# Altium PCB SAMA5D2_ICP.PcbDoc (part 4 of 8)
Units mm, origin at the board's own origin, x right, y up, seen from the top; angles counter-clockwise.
Board outline 150 x 100 mm, 6 copper layers (L1 - TOP, L2 - GND, L3 - SIG, L4 - SIG, L5 - VCC, L6 - BOT), stack 1.512 mm thick; 708 components, 597 nets, 2710 pads, 1437 vias.
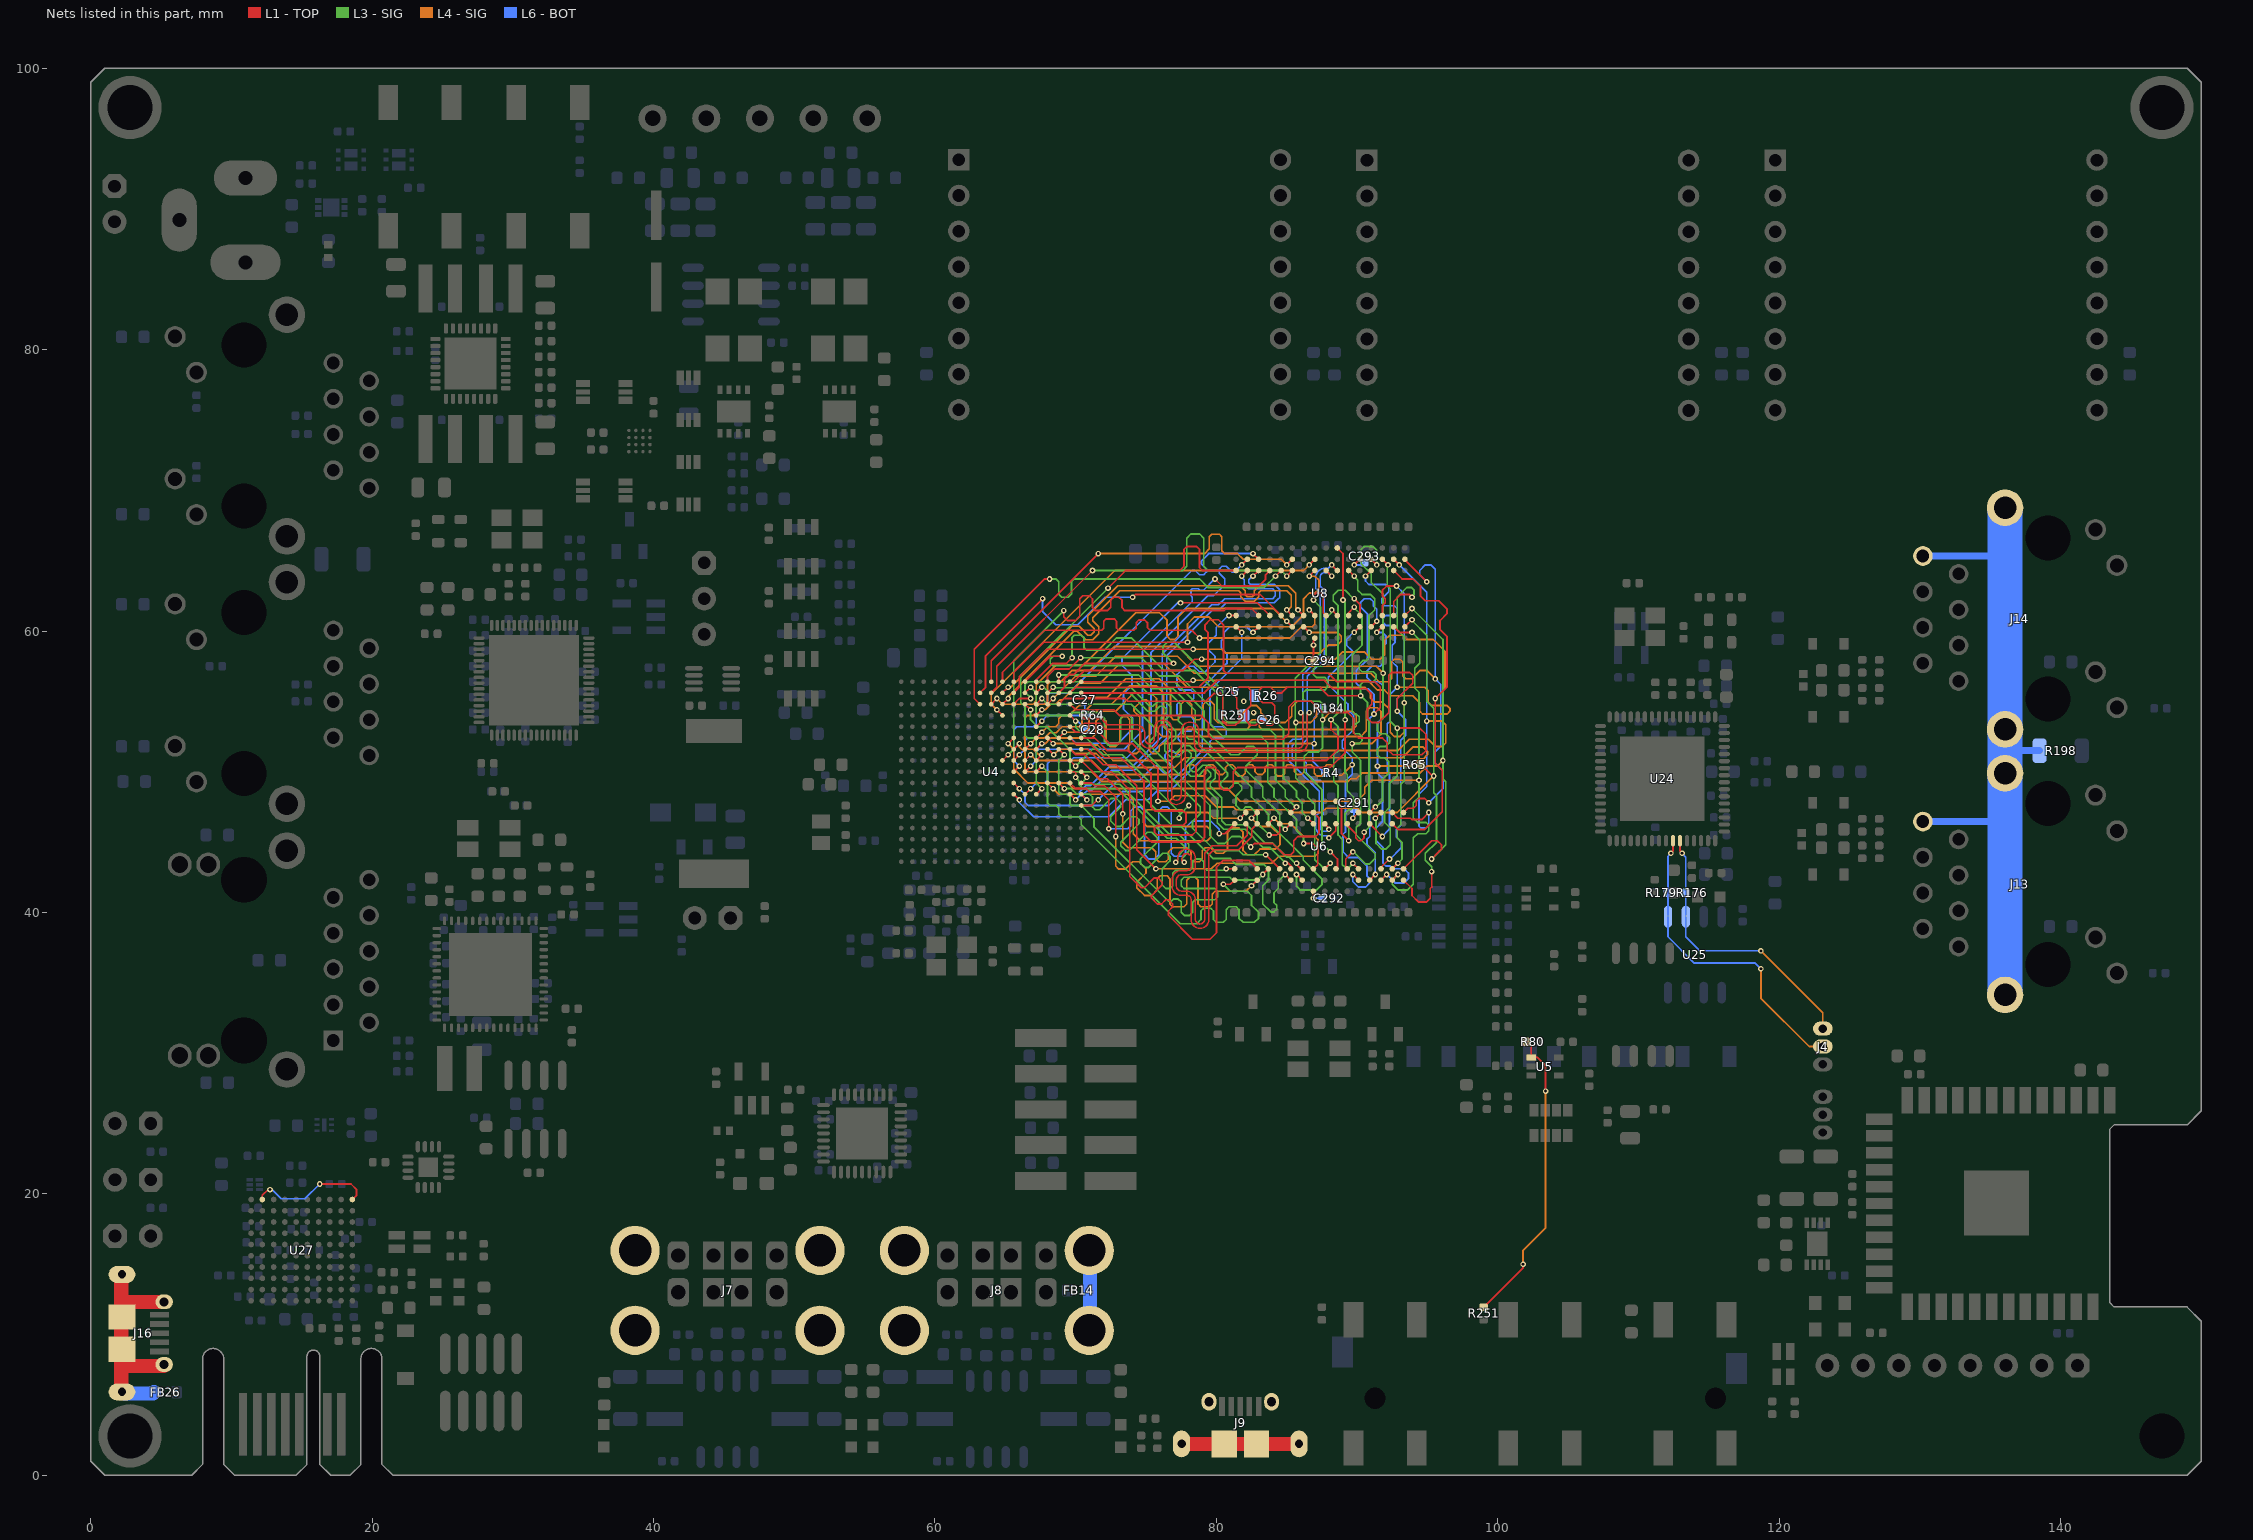
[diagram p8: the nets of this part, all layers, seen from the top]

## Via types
v1: diameter 0.4, hole 0.2, L1 - TOP to L6 - BOT, tented both sides, 1312 vias
v2: diameter 0.55, hole 0.3, L1 - TOP to L6 - BOT, 84 vias
v3: diameter 0.4, hole 0.2, L1 - TOP to L6 - BOT, tented top, 25 vias
v4: diameter 0.55, hole 0.3, L1 - TOP to L6 - BOT, tented bottom, 16 vias

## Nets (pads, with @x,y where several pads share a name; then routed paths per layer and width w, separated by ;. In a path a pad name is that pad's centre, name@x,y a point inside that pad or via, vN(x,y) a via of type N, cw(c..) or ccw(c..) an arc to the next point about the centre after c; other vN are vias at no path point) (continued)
DDR_A2: U4.B17 U6.P3 U8.P3 | length 57.6
  L1 - TOP w0.125: U4.B17@70.4,55.6 79.15,55.6 80.05,56.5 87.65,56.5 88.25,55.9 90.65,55.9 91.05,55.5 91.05,54.793 90.75,54.493 90.75,53.8 91.05,53.5 91.55,53.5 92.25,54.2 92.25,56.85 92.45,57.05 93.75,57.05 93.95,56.85 93.95,56.3 92.85,55.2 v1(92.85,54.3) ; U6.P3@91.7,43.1 91.7,43.2 v1(92.3,43.8) ; U8.P3@91.8,61.1 91.8,61.8 92,62 92,62.3 91.8,62.5 91.8,62.9 92.1,63.2 v1(92.8,63.2)
  L6 - BOT w0.125: v1@92.35,43.8 93.15,44.6 93.15,44.993 92.8,45.343 92.8,45.9 93.1,46.2 93.1,52.25 93.45,52.6 93.45,53.7 v1(92.85,54.3) 92.85,55.2 93.35,55.7 93.35,62.65 v1(92.8,63.2)
DDR_A3: U4.B16 U6.N2 U8.N2 | length 57.5
  L1 - TOP w0.125: U4.B16@69.6,55.6 70,56 78.75,56 79.4,56.65 79.4,59.9 79.2,60.1 79.2,60.45 79.55,60.8 80.15,60.8 80.5,60.45 80.5,57.2 80.7,57 87.95,57 88.55,56.4 91.25,56.4 91.65,56 91.65,54.55 v1(91.2,54.1) ; U6.N2@90.9,42.3 v1(91.3,42.7) ; U8.N2@91,60.3 v1(91.4,60.7)
  L6 - BOT w0.125: v1(91.3,42.7) 91.3,44.25 90.7,44.85 90.7,45.2 90.9,45.4 90.9,53.8 v1(91.2,54.1) 91.2,55.5 90.8,55.9 90.35,55.9 89.95,56.3 89.95,57.193 90.75,57.993 90.75,61.2 90.25,61.7 90.25,62.05 90.5,62.3 90.95,62.3 91.15,62.1 91.15,61.8 91.4,61.55 v1(91.4,60.7)
DDR_A4: U4.C16 U6.P8 U8.P8 | length 60
  L1 - TOP w0.125: U4.C16@69.6,54.8 70,54.4 72.7,54.4 73.1,54 78.9,54 79.45,53.45 79.45,52.55 79.7,52.3 84.75,52.3 85.15,52.7 85.15,54.6 85.55,55 86.75,55 87.55,54.2 89.357,54.2 89.75,53.807 89.75,52.75 90.1,52.4 91.8,52.4 92.15,52.05 92.15,51.6 92.55,51.2 94.6,51.2 94.9,51.5 94.9,52.65 94.45,53.1 v1(92.85,53.1) ; v1(91.3,46.7) U6.P8@91.7,47.1 ; U8.P8@91.8,65.1 v1(92.2,64.7)
  L3 - SIG w0.125: v1@91.35,46.7 91.35,44.9 91.75,44.5 92.05,44.5 92.35,44.8 92.35,46 91.95,46.4 91.95,47.1 92.3,47.45 92.3,49.15 92.85,49.7 v1(92.85,53.1) 92.35,53.6 92.35,63.009 92.15,63.209 v1@92.15,64.7
DDR_A5: U4.G14 U6.P2 U8.P2 | length 57.5
  L1 - TOP w0.125: U4.G14@68.05,51.6 v1(68.45,51.2) ; v1(91.4,59.9) U8.P2@91.8,60.3 ; U6.P2@91.7,42.3 v1(92.1,42.7)
  L4 - SIG w0.125: v1(68.45,51.2) 68.85,51.6 69.65,51.6 69.95,51.3 71.45,51.3 72.45,50.3 77.05,50.3 77.75,51 93.2,51 93.95,51.75 94.7,51.75 95,51.45 95,51.2 94.7,50.9 94.4,50.9 93.9,50.4 v1(91.45,50.4)
  L6 - BOT w0.125: v1(91.4,59.9) 91.8,59.9 92.05,59.65 92.05,59.1 91.85,58.9 91.85,57.7 91.65,57.5 91.05,57.5 90.7,57.15 90.7,56.7 91,56.4 91.55,56.4 91.85,56.1 91.85,53.9 91.45,53.5 v1(91.45,50.4) 91.45,49.9 91.8,49.55 91.8,46.45 91.35,46 91.35,45.1 91.85,44.6 91.85,43.5 92.05,43.3 92.35,43.3 92.55,43.1 93.35,43.1 93.65,42.8 93.65,42.4 93.35,42.1 92.7,42.1 v1(92.1,42.7)
DDR_A6: U4.F14 U6.R8 U8.R8 | length 57.6
  L1 - TOP w0.125: U4.F14@68,52.4 v1(68.4,52) ; U6.R8@92.5,47.1 92.9,46.7 93.8,46.7 93.9,46.6 94.6,46.6 v1(95.1,47.1) v1@95.1,47.125 ; U8.R8@92.6,65.1 v1(93,64.7)
  L4 - SIG w0.125: v1(68.4,52) 69.95,52 70.05,51.9 71.557,51.9 72.657,50.8 76.75,50.8 77.45,51.5 92.9,51.5 93.7,52.3 95.05,52.3 95.55,51.8 96.06,51.8 96.3,52.04 96.3,53.325 96.025,53.6 v1(94.95,53.6)
  L6 - BOT w0.125: v1(93,64.7) 94.95,62.75 v1(94.95,53.6) 94.95,48.95 94.4,48.4 94.4,46.128 94.528,46 94.922,46 95.1,46.178 v1(95.1,47.1)
DDR_A7: U4.F11 U6.R2 U8.R2 | length 58.1
  L1 - TOP w0.125: v1(65.2,52) U4.F11@65.6,52.4 ; U6.R2@92.5,42.3 v1(92.9,42.7) ; U8.R2@92.6,60.3 93,59.9 v1(93.9,59.9)
  L3 - SIG w0.125: v1(92.9,42.7) 92.5,42.3 92.5,42 92.9,41.6 93.6,41.6 94,42 94,45.3 94.3,45.6 94.9,45.6 95.1,45.8 95.1,46.2 94.9,46.4 94.3,46.4 94,46.7 94,47.8 94.4,48.2 v1(94.4,49.4) 94.4,55.65 94.1,55.95 94.1,57.35 94.45,57.7 94.45,59.35 v1(93.9,59.9)
  L4 - SIG w0.125: v1(65.2,52) 65.6,51.6 65.6,50.2 66.6,49.2 69.45,49.2 69.85,48.8 80.8,48.8 81.7,47.9 90,47.9 90.55,48.45 90.55,48.9 91.05,49.4 v1(94.4,49.4)
DDR_A8: U4.C14 U6.T8 U8.T8 | length 57.4
  L1 - TOP w0.125: U4.C14@68,54.8 v1(68.4,55.2) ; U8.T8@93.35,65.1 v1(94.95,63.5) ; U6.T8@93.4,47.2 93.6,47.4 94,47.4 94.2,47.6 94.2,47.9 94.4,48.1 94.8,48.1 v1(95.1,47.8)
  L4 - SIG w0.125: v1(68.4,55.2) 70,56.8 71.45,56.8 72.85,58.2 77.236,58.2 78.436,57 90.964,57 ; 90.964,56.996 91.56,56.4 92.25,56.4 92.45,56.6 92.45,57.8 92.65,58 93.05,58 93.25,57.8 93.25,56.8 93.45,56.6 93.9,56.6 94.5,57.2 94.95,57.2 v1(95.55,56.6)
  L6 - BOT w0.125: v1(94.95,63.5) 94.45,64 94.45,64.3 94.85,64.7 95.25,64.7 95.55,64.4 v1(95.55,56.6) 95.95,56.2 95.95,51.8 95.45,51.3 95.45,50.7 96.1,50.05 96.1,48.8 v1(95.1,47.8)
DDR_A9: U4.D13 U6.R3 U8.R3 | length 58.1
  L1 - TOP w0.125: U4.D13@67.2,54 v1(67.6,54.4) ; U6.R3@92.5,43.1 v1(92.9,43.5) ; U8.R3@92.6,61.1 92.6,62.1 93.1,62.6 93.7,62.6 v1(93.9,62.4)
  L3 - SIG w0.125: v1(92.9,43.5) 93.2,43.8 93.2,44.95 92.85,45.3 92.85,46 93.1,46.25 93.1,49.1 93.35,49.35 v1(93.35,54.9) 93.35,59.6 92.85,60.1 92.85,62.4 93.55,63.1 93.85,63.1 94.05,62.9 94.05,62.6 v1@93.85,62.4
  L4 - SIG w0.125: v1(67.6,54.4) 67.834,54.4 68.234,54.8 68.566,54.8 68.866,55.1 69.05,55.1 70.25,56.3 71.75,56.3 73.15,57.7 76.243,57.7 77.943,56 90.543,56 90.946,55.596 90.946,55.25 91.246,54.95 91.8,54.95 92.35,54.4 92.35,52.8 92.65,52.5 93.043,52.5 93.35,52.807 v1(93.35,54.9)
DDR_A10: U4.C15 U6.L7 U8.L7 | length 60
  L1 - TOP w0.125: U4.C15@68.8,54.8 69.2,55.2 73.5,55.2 73.7,55 79.257,55 79.807,55.55 80.3,55.55 80.45,55.4 80.45,53.6 80.75,53.3 81.35,53.3 81.65,53.6 81.65,54.3 81.45,54.5 81.45,55.25 81.15,55.55 81.15,55.8 81.35,56 82.25,56 82.45,55.8 82.45,54.707 82.15,54.407 82.15,53.6 82.45,53.3 82.8,53.3 83.1,53.6 83.3,53.6 83.6,53.3 83.95,53.3 84.15,53.5 84.15,54.7 83.95,54.9 83.3,54.9 83.05,55.15 83.05,55.8 83.25,56 83.85,56 84.25,55.6 84.65,55.6 85.05,56 87.35,56 87.95,55.4 v1(90.25,55.4) ; U6.L7@89.3,46.2 89.9,45.6 89.9,45.3 90.1,45.1 90.3,45.1 90.5,45.3 v1(90.5,45.7) ; U8.L7@89.4,64.3 v1(89.8,63.9)
  L3 - SIG w0.125: v1@89.75,63.9 90.05,63.6 90.05,62.9 90.35,62.6 90.95,62.6 91.25,62.3 91.25,61.493 90.85,61.093 90.85,58.1 90.65,57.9 90.4,57.9 90.15,57.65 90.15,57.3 90.35,57.1 91.15,57.1 91.35,56.9 91.35,56.6 91.15,56.4 90.45,56.4 90.25,56.2 v1(90.25,55.4) 90.75,54.9 90.75,53.7 90.85,53.6 90.85,46.05 v1(90.5,45.7)
DDR_A11: U4.A16 U6.R7 U8.R7 | length 58.1
  L1 - TOP w0.125: U4.A16@69.6,56.4 69.85,56.4 70.65,57.2 77.65,57.2 78.45,58 v1(78.95,58) ; U6.R7@92.5,46.3 92.9,45.9 94.8,45.9 96.05,47.15 96.05,50.1 95.55,50.6 v1(95.55,55.2) 96.4,56.05 96.4,59.6 95.9,60.1 95.9,60.75 96.4,61.25 96.4,61.55 95.8,62.15 94.85,62.15 94.5,62.5 94.5,63.2 94,63.7 93.2,63.7 U8.R7@92.6,64.3
  L4 - SIG w0.125: v1(78.95,58) 88.45,58 88.95,58.5 90.55,58.5 91.05,58 91.65,58 91.95,58.3 91.95,59.325 92.325,59.7 93.25,59.7 93.55,59.4 95.4,59.4 96.25,58.55 96.25,55.9 v1(95.55,55.2)
DDR_A12: U4.A17 U6.N7 U8.N7 | length 57.6
  L1 - TOP w0.125: U4.A17@70.4,56.4 78.25,56.4 v1(78.35,56.5) ; v1(90.6,63.9) U8.N7@91,64.3 ; U6.N7@90.9,46.3 v1(91.8,45.4)
  L4 - SIG w0.125: v1(78.35,56.5) 90.75,56.5 91.45,55.8 91.95,55.8 92.35,55.4 93.95,55.4 94.45,54.9 94.45,54.3 94.65,54.1 96.4,54.1 96.6,54.3 96.6,54.5 96.4,54.7 95.3,54.7 95.05,54.95 95.05,55.75 94.8,56 v1(92.85,56)
  L6 - BOT w0.125: v1(90.6,63.9) 90.6,63.55 90.85,63.3 92.05,63.3 92.25,63.1 92.25,62.8 91.75,62.3 91.75,62 91.95,61.8 92.65,61.8 92.85,61.6 92.85,61.3 92.65,61.1 92.05,61.1 91.85,60.9 91.85,60.6 92.05,60.4 92.35,60.4 92.7,60.05 92.7,59.2 92.5,59 92.5,57.8 92.85,57.45 v1(92.85,56) 92.35,55.5 92.35,53.6 92.15,53.4 92.15,50 92.3,49.85 92.3,45.9 v1(91.8,45.4)
DDR_A13: U4.G11 U6.T3 U8.T3 | length 58.1
  L1 - TOP w0.125: U4.G11@65.6,51.6 v1(66,52) ; U6.T3@93.3,43.1 95.3,45.1 95.7,45.1 96,44.8 96,44.5 95.8,44.3 v1(95.3,43.8) ; U8.T3@93.4,61.1 v1(93.9,61.6)
  L3 - SIG w0.125: v1(93.9,61.6) 96.1,59.4 v1(96.1,50.8) 96.1,49.5 96.3,49.3 96.3,44.8 v1(95.3,43.8)
  L4 - SIG w0.125: v1(66,52) 66,51.775 66.4,51.375 66.4,50.2 66.6,50 71.15,50 71.85,49.3 89.343,49.3 89.543,49.5 89.95,49.5 90.35,49.9 94.45,49.9 94.95,50.4 95.7,50.4 v1(96.1,50.8)
DDR_BA0: U4.H12 U6.M2 U8.M2 | length 57.6
  L1 - TOP w0.125: U4.H12@66.4,50.8 v1(66.8,51.2) ; v1(89.7,42.7) U6.M2@90.1,42.3 ; v1(89.8,59.9) U8.M2@90.2,60.3
  L4 - SIG w0.125: v1(66.8,51.2) 67.2,50.8 71.15,50.8 71.45,50.5 72.15,49.8 77.65,49.8 77.85,50 77.85,50.3 78.05,50.5 78.35,50.5 78.55,50.3 78.55,49.89 78.75,49.69 79.05,49.69 79.25,49.89 79.25,50.3 79.45,50.5 79.75,50.5 79.95,50.3 79.95,50 80.15,49.8 80.45,49.8 80.65,50 80.65,50.3 80.85,50.5 81.15,50.5 81.35,50.3 81.35,49.89 81.55,49.69 81.85,49.69 82.05,49.89 82.05,50.3 82.25,50.5 82.55,50.5 82.75,50.3 ; 82.75,50.3 82.75,50 82.95,49.8 83.25,49.8 83.45,50 83.45,50.3 83.65,50.5 83.95,50.5 84.15,50.3 84.15,49.89 84.35,49.69 84.65,49.69 84.85,49.89 84.85,50.3 85.05,50.5 85.35,50.5 85.55,50.3 85.55,50 85.75,49.8 86.05,49.8 86.25,50 86.25,50.3 86.45,50.5 86.75,50.5 86.95,50.3 86.95,49.89 87.15,49.69 87.45,49.69 87.65,49.89 87.65,50.3 87.85,50.5 88.15,50.5 88.35,50.3 88.35,49.9 88.5,49.75 88.9,49.75 v1(89.65,50.5)
  L6 - BOT w0.125: v1(89.7,42.7) 89.7,42.2 90.1,41.8 90.6,41.8 90.9,42.1 90.9,42.4 90.7,42.6 90.7,43.3 90.1,43.9 89.4,43.9 89,44.3 89,45.55 89.175,45.725 89.175,49.35 89.65,49.825 v1(89.65,50.5) 89.65,51.01 88.95,51.71 88.95,52.19 89.75,52.99 89.75,54 89.35,54.4 89.35,54.81 87.96,56.2 87.95,56.2 87.95,56.7 89.65,58.4 89.65,58.6 89.25,59 89.25,59.4 v1@89.75,59.9
DDR_BA1: U4.H13 U6.N8 U8.N8 | length 57.9
  L1 - TOP w0.125: U4.H13@67.2,50.8 v1(67.6,51.2) ; U6.N8@90.9,47.1 v1(91.3,47.5) ; U8.N8@91,65.1 v1(91.4,64.7)
  L3 - SIG w0.125: v1@91.35,47.5 91.8,47.95 91.8,49.45 92.25,49.9 92.25,50.7 91.95,51 91.65,51 91.45,51.2 91.45,51.6 91.65,51.8 92.05,51.8 92.3,52.05 92.3,52.45 92.05,52.7 91.65,52.7 91.45,52.9 91.45,53.4 91.85,53.8 v1(91.85,57) 91.85,62.6 91,63.45 91,64.066 90.3,64.766 90.3,65.8 90.5,66 91.15,66 91.4,65.75 v1(91.4,64.7)
  L4 - SIG w0.125: v1(67.6,51.2) 67.374,51.2 66.974,51.6 66.634,51.6 66.4,51.834 66.4,53.825 66.575,54 67,54 67.2,54.2 67.2,54.6 67.4,54.8 67.775,54.8 68,55.025 68,56.175 68.225,56.4 68.95,56.4 69.75,57.2 71.05,57.2 72.75,58.9 77.243,58.9 78.643,57.5 91.35,57.5 v1(91.85,57)
DDR_BA2: U4.F17 U6.M3 U8.M3 | length 59.9
  L1 - TOP w0.125: U4.F17@70.4,52.4 71.35,52.4 72.25,51.5 73.75,51.5 75.35,49.9 75.35,47.5 75.65,47.2 77.65,47.2 77.85,47 77.85,46.4 77.65,46.2 75.802,46.2 75.602,46 75.602,45.7 75.802,45.5 78.3,45.5 78.55,45.75 78.55,50.4 78.95,50.8 87.85,50.8 88.65,51.6 88.65,52.5 88.15,53 v1(88.15,53.7) ; v1(89.7,43.5) U6.M3@90.1,43.1 ; v1(89.8,62.3) 90.2,61.9 U8.M3@90.2,61.1
  L3 - SIG w0.125: v1@89.725,43.475 89.45,43.2 89.15,43.2 88.95,43.4 88.95,45.2 88.65,45.5 88.65,49.007 88.35,49.307 88.35,51.2 88.65,51.5 88.65,53.2 v1(88.15,53.7) 88.65,54.2 88.65,61.8 88.3,62.15 88.3,62.55 88.65,62.9 89.15,62.9 v1@89.75,62.3
DDR_CAL: C27.2 R64.2 U4.E13 | length 4.4
  L1 - TOP w0.125: U4.E13@67.2,53.2 v1(67.6,53.6)
  L6 - BOT w0.125: v1(67.6,53.6) 68,54 R64.2@70.55,54 ; R64.2@70.65,54.1 C27.2@70.65,54.8
DDR_CAS: U4.G12 U6.K3 U8.K3 | length 58
  L1 - TOP w0.125: U4.G12@66.4,51.6 v1(66.8,52) ; v1(88.1,44.3) 88.6,43.8 U6.K3@88.6,43.2 ; v1(88.2,61.5) U8.K3@88.6,61.1
  L3 - SIG w0.125: v1(88.1,44.3) 87.5,44.9 87.5,48.75 86.25,50 86.25,51.1 86.55,51.4 87.25,51.4 87.55,51.7 v1(87.55,53.7) 87.55,54.8 87.35,55 86.35,55 86.15,55.2 86.15,55.6 86.35,55.8 87.7,55.8 87.9,56 87.9,56.5 87.7,56.7 87.1,56.7 86.9,56.9 86.9,57.3 87.1,57.5 87.5,57.5 87.8,57.8 87.8,60.916 88.15,61.266 v1@88.15,61.5
  L4 - SIG w0.125: v1(66.8,52) 67.2,52.4 67.775,52.4 68.15,52.775 68.609,52.775 69.034,53.2 70.25,53.2 70.45,53.4 70.45,54.1 71.15,54.8 72.55,54.8 73.85,56.1 75.722,56.1 76.25,55.572 76.25,53.2 76.45,53 80.55,53 82.15,53 82.35,53.2 82.35,53.5 82.55,53.7 82.85,53.7 83.05,53.5 83.05,53.2 83.25,53 89.7,53 89.95,53.25 89.95,54 89.65,54.3 88.15,54.3 v1(87.55,53.7)
DDR_CKE: U4.F16 U6.K9 U8.K9 | length 60
  L1 - TOP w0.125: U4.F16@69.6,52.4 70,52 71.05,52 72.05,51 73.225,51 74.85,49.375 74.85,45.55 75.4,45 78.845,45 79.15,45.305 79.15,50.05 79.4,50.3 79.9,50.3 80.2,50 80.2,49 80.5,48.7 80.9,48.7 81.2,49 81.2,50 81.5,50.3 88.1,50.3 89.15,51.35 v1(89.15,53.7) ; U6.K9@88.5,47.9 88.9,47.5 88.9,45.6 v1(89.4,45.1) ; U8.K9@88.6,65.9 89,65.5 v1(89,62.2)
  L3 - SIG w0.125: v1(89,62.2) 89.15,62.05 v1(89.15,53.7) 89.15,49.95 89.3,49.8 89.3,48.65 89.75,48.2 89.75,47.5 89.55,47.3 89.4,47.3 89.15,47.05 89.15,46.25 89.4,46 v1(89.4,45.1)
DDR_CLK_N: U4.D17 U6.K7 U8.K7 | length 57.3
  L1 - TOP w0.102: U4.D17@70.4,54 70.648,53.752 71.823,53.752 72.244,53.331 74.294,53.331 cw(c74.294,52.7) 74.924,52.7 74.924,52.3 ccw(c75.25,52.3) 75.25,51.974 ccw(c75.25,52.3) 75.576,52.3 75.576,53.026 cw(c76.207,53.026) 76.207,53.656 cw(c76.207,53.026) 76.837,53.026 76.837,48.3 ccw(c77.163,48.3) 77.163,47.974 ccw(c77.163,48.3) 77.489,48.3 77.489,52.884 cw(c78.119,52.884) 78.119,53.515 cw(c78.119,52.884) 78.75,52.884 78.75,52 ccw(c79.076,52) 79.076,51.674 79.35,51.674 85.824,51.674 ccw(c85.824,52) 86.15,52 86.15,54.05 v1(86,54.2) ; v1@88.1,45.4 88.5,45.8 U6.K7@88.5,46.3 ; v1(88.2,64.7) U8.K7@88.5,64.4
  L6 - BOT w0.102: v1(86,54.2) v1@86.145,54.2 ; v1(88,45.3) 87.853,45.448 87.7,45.448 cw(c87.7,46.078) 87.069,46.078 87.069,46.869 87.295,47.095 87.295,48.605 85.1,50.8 85.1,51.981 85.419,52.3 86,52.3 86.145,52.445 v1@86.145,54.2 ; v1(88.2,64.7) 87.952,64.452 87.7,64.452 ccw(c87.7,63.822) 87.069,63.822 87.069,63.05 87.37,62.749 87.37,58.12 86.145,56.895 v1@86.145,54.2
DDR_CLK_P: U4.E17 U6.J7 U8.J7 | length 57.1
  L1 - TOP w0.102: U4.E17@70.4,53.2 70.648,53.448 71.696,53.448 72.118,53.026 74.294,53.026 cw(c74.294,52.7) 74.62,52.7 74.62,52.3 ccw(c75.25,52.3) 75.25,51.669 ccw(c75.25,52.3) 75.881,52.3 75.881,53.026 cw(c76.207,53.026) 76.207,53.352 cw(c76.207,53.026) 76.532,53.026 76.532,48.3 ccw(c77.163,48.3) 77.163,47.669 ccw(c77.163,48.3) 77.794,48.3 77.794,52.884 cw(c78.119,52.884) 78.119,53.21 cw(c78.119,52.884) 78.445,52.884 78.445,52 ccw(c79.076,52) 79.076,51.369 79.35,51.369 85.824,51.369 ccw(c85.824,52) 86.455,52 86.455,54.055 v1(86.6,54.2) ; U6.J7@87.7,46.3 88,46 v1(88,45.9) ; U8.J7@87.8,64.3 v1(88.2,63.9)
  L6 - BOT w0.102: v1(86.6,54.2) v1@86.45,54.2 ; v1(88,45.9) 87.853,45.752 87.7,45.752 cw(c87.7,46.078) 87.374,46.078 87.374,46.743 87.6,46.969 87.6,49.2 87.4,49.4 86.931,49.4 86.4,49.931 86.4,50.639 86.239,50.8 85.531,50.8 85.405,50.926 85.405,51.855 85.545,51.995 86.126,51.995 86.45,52.319 v1@86.45,54.2 ; v1(88.2,63.9) 87.952,64.148 87.7,64.148 ccw(c87.7,63.822) 87.374,63.822 87.374,63.176 87.675,62.875 87.675,57.994 86.45,56.769 v1@86.45,54.2
DDR_CS: R4.1 R184.1 U4.G13 | length 40.4
  L1 - TOP w0.125: U4.G13@67.2,51.6 v1(67.6,52)
  L4 - SIG w0.125: v1(67.6,52) 67.834,52 68.234,52.4 71.15,52.4 71.45,52.7 71.45,53.6 71.65,53.8 71.95,53.8 72.15,53.6 72.15,52.1 72.45,51.8 72.85,51.8 73.15,52.1 73.15,53.7 73.35,53.9 73.65,53.9 73.85,53.7 73.85,51.9 73.75,51.8 73.75,51.5 73.95,51.3 74.35,51.3 74.55,51.5 74.55,53.9 74.15,54.3 74.15,54.5 74.75,55.1 75.05,55.1 75.25,54.9 75.25,51.5 75.45,51.3 75.75,51.3 75.95,51.5 75.95,51.8 76.15,52 v1(86.95,52)
  L6 - BOT w0.125: R184.1@87.6,54.5 86.95,53.85 v1(86.95,52) 86.85,51.9 86.85,50.75 R4.1@87.7,49.9
DDR_D0: U4.B12 U6.E3 | length 30.7
  L1 - TOP w0.125: U4.B12@66.4,55.6 v1(66.8,56) ; v1(83.5,44.1) U6.E3@84.5,43.1
  L3 - SIG w0.125: v1(66.8,56) 67.2,55.6 67.2,54.225 67.425,54 69.55,54 69.75,54.2 71.65,54.2 72.05,53.8 72.05,52.15 72.3,51.9 72.9,51.9 73.2,52.2 73.2,53.8 73.4,54 73.8,54 74,53.8 74,52.35 78.85,47.5 78.85,47 78.3,46.45 78.3,46 79.9,44.4 81.6,44.4 81.9,44.1 v1(83.5,44.1)
DDR_D1: U4.A12 U6.F7 | length 30.8
  L1 - TOP w0.125: U4.A12@66.4,56.4 68.2,58.2 v1(69.05,58.2) ; v1(84.9,45.9) U6.F7@85.3,46.3
  L3 - SIG w0.125: v1(69.05,58.2) 68.4,58.2 68.2,58 68.2,57.7 68.35,57.55 74.466,57.55 75.65,56.366 77.084,56.366 79.116,54.334 79.116,53.109 81.025,51.2 81.6,51.2 82.2,51.8 82.626,51.8 82.9,51.526 82.9,51.2 82.1,50.4 82.1,50.125 83.3,48.925 83.3,48.2 84.5,47 84.5,46.3 v1(84.9,45.9)
DDR_D2: U4.C12 U6.F2 | length 30.8
  L1 - TOP w0.125: U4.C12@66.4,54.8 v1(66.8,54.4) ; v1(84.9,42.7) U6.F2@85.3,42.3
  L3 - SIG w0.125: v1(66.8,54.4) 66.8,53.687 67.288,53.2 67.95,53.2 69.6,51.55 69.6,50.225 69.825,50 73.043,50 76.943,46.1 77.5,46.1 79.775,43.825 81,43.825 81.425,43.4 83.4,43.4 83.7,43.1 83.7,42.3 83.3,41.9 83.3,40.6 83.863,40.037 84.1,40.037 84.3,40.237 84.3,40.5 84.1,40.7 84.1,41.4 84.4,41.7 84.4,42.2 v1(84.9,42.7)
DDR_D3: U4.A13 U6.F8 | length 30.8
  L1 - TOP w0.125: U4.A13@67.2,56.4 67.2,56.54 68.36,57.7 69.35,57.7 v1(69.75,58.1) ; U6.F8@85.3,47.1 v1(85.7,47.5)
  L3 - SIG w0.125: v1(69.75,58.1) 69.75,59.55 69.9,59.7 70.407,59.7 70.6,59.507 70.6,58.8 70.775,58.625 72.025,58.625 72.907,59.507 73.943,59.507 76.25,57.2 78.434,57.2 80.05,55.584 80.05,53.734 80.784,53 83.8,53 84.2,52.6 84.2,49.4 84.9,48.7 84.9,48.2 85.6,47.5 v1(85.7,47.5)
DDR_D4: U4.A14 U6.H3 | length 30.7
  L1 - TOP w0.125: U4.A14@68,56.4 68,56.775 68.525,57.3 69.55,57.3 v1(70.35,58.1) ; v1(86.2,44.9) 86.85,44.9 87.2,44.55 87.2,43.4 U6.H3@86.9,43.1
  L3 - SIG w0.125: v1(70.35,58.1) 74.65,58.1 75.95,56.8 77.4,56.8 79.6,54.6 79.6,53.35 80.45,52.5 83.2,52.5 83.658,52.042 83.658,49.242 84.1,48.8 84.1,48.2 85.7,46.6 85.7,45.8 86.2,45.3 v1(86.2,44.9)
DDR_D5: U4.C13 U6.H8 | length 30.7
  L1 - TOP w0.125: U4.C13@67.2,54.8 v1(67.6,55.2) ; v1(82.45,44.65) 82.7,44.9 84.013,44.9 84.813,44.1 85.3,44.1 85.5,44.3 85.5,45.105 85.795,45.4 87.05,45.4 87.3,45.65 87.3,46.7 U6.H8@86.9,47.1
  L3 - SIG w0.125: v1(67.6,55.2) 68,54.8 73.95,54.8 75.7,53.05 75.7,52.6 75.3,52.2 75.3,51.85 79.55,47.6 79.55,45.45 80.1,44.9 80.6,44.9 81.1,45.4 81.7,45.4 v1(82.45,44.65)
DDR_D6: U4.A15 U6.G2 | length 30.8
  L1 - TOP w0.125: U4.A15@68.8,56.4 v1(68.8,56.875) ; v1(85.7,42.7) U6.G2@86.1,42.3
  L3 - SIG w0.125: v1(68.8,56.875) 74.475,56.875 75.45,55.9 76.95,55.9 78.5,54.35 78.5,52.9 82.5,48.9 82.5,48.2 83.7,47 83.7,46.425 86.175,43.95 86.175,43.725 87.5,42.4 87.5,41.975 87.125,41.6 85.95,41.6 85.7,41.85 v1(85.7,42.7)
DDR_D7: U4.B15 U6.H7 | length 30.8
  L1 - TOP w0.125: U4.B15@68.8,55.6 69.2,56 69.2,56.566 69.534,56.9 69.857,56.9 70.657,57.7 v1(76.95,57.7) ; v1(86.5,46.7) U6.H7@86.9,46.3
  L3 - SIG w0.125: v1(76.95,57.7) 76.2,58.45 76.2,58.9 76.5,59.2 77,59.2 80.45,55.75 80.45,53.9 80.85,53.5 84.3,53.5 84.775,53.025 84.775,49.525 85.7,48.6 85.7,48.2 85.9,48 86.1,47.8 86.1,47.1 v1(86.5,46.7)
DDR_D8: U4.G17 U6.D7 | length 28.7
  L1 - TOP w0.125: U4.G17@70.4,51.6 70.85,51.6 71.95,50.5 72.85,50.5 74.35,49 74.35,44.45 v1(75.7,43.1) ; U6.D7@83.7,46.3 v1(84.1,46.7)
  L4 - SIG w0.125: v1(75.7,43.1) 79.65,43.1 80.05,43.5 83.95,43.5 84.45,44 87,44 87.224,44.224 87.224,45.176 87,45.4 86.2,45.4 85.3,46.3 84.5,46.3 v1(84.1,46.7)
DDR_D9: U4.G16 U6.C3 | length 31.3
  L1 - TOP w0.125: U4.G16@69.6,51.6 70,51.2 70.65,51.2 71.85,50 72.55,50 73.85,48.7 73.85,42.55 74.65,41.75 74.891,41.75 75.595,42.455 75.855,42.455 76.155,42.155 76.155,41.955 75.4,41.2 75.4,41 75.8,40.6 76.1,40.6 76.4,40.9 76.6,40.9 76.9,40.6 76.9,40.4 76.6,40.1 76.6,39.8 78.3,38.1 79.55,38.1 80.012,38.562 80.012,43.212 80.5,43.7 82.3,43.7 U6.C3@82.9,43.1
DDR_D10: U4.H17 U6.C8 | length 28.8
  L1 - TOP w0.125: U4.H17@70.4,50.8 71.7,49.5 72.257,49.5 73.35,48.407 v1(73.35,47) ; v1(82.5,46.7) U6.C8@82.9,47.1
  L4 - SIG w0.125: v1(73.35,47) 73.35,45 73.75,44.6 75.4,44.6 75.7,44.3 75.7,43.8 75.9,43.6 76.4,43.6 76.6,43.8 76.6,44.3 76.9,44.6 77.9,44.6 78.2,44.3 78.2,43.8 78.4,43.6 78.8,43.6 79,43.8 79,44.4 79.2,44.6 79.6,44.6 80,44.2 80.5,44.2 80.8,44.5 80.8,45.7 81.1,46 81.6,46 81.9,45.7 81.9,44.4 82.2,44.1 82.7,44.1 83.1,44.5 84.2,44.5 84.531,44.831 84.531,45.469 83.9,46.1 83.1,46.1 82.525,46.675 v1(82.5,46.7)
DDR_D11: U4.K17 U6.C2 | length 28.8
  L1 - TOP w0.125: U4.K17@70.4,49.2 71.15,49.2 71.35,49 72.05,49 72.85,48.2 v1(72.85,45.4) ; v1(82.5,41.9) U6.C2@82.9,42.3
  L4 - SIG w0.125: v1(72.85,45.4) 72.85,43.3 73.072,43.078 73.528,43.078 74.05,43.6 74.5,43.6 75,43.1 75,42.8 74.35,42.15 74.35,41.75 74.9,41.2 75.4,41.2 75.8,41.6 75.8,42.4 76,42.6 76.5,42.6 76.7,42.4 76.7,40.6 76.9,40.4 77.7,40.4 77.9,40.6 77.9,42.3 78.1,42.5 78.5,42.5 78.7,42.3 78.7,40.6 78.9,40.4 79.5,40.4 79.7,40.6 79.7,41.301 79.9,41.501 82.101,41.501 v1(82.5,41.9)
DDR_D12: U4.K16 U6.A7 | length 28.3
  L1 - TOP w0.125: U4.K16@69.6,49.2 70,48.8 70.75,48.8 70.95,48.6 71.743,48.6 72.35,47.993 v1(72.35,45.95) ; v1(80.2,45.6) 80.6,45.6 U6.A7@81.3,46.3
  L6 - BOT w0.125: v1(72.35,45.95) 73.7,45.95 73.9,46.15 73.9,47.2 74.2,47.5 74.6,47.5 74.9,47.2 74.9,44.1 75.2,43.8 75.6,43.8 75.9,44.1 75.9,47.2 76.2,47.5 76.5,47.5 76.8,47.2 76.8,44.2 77,44 77.6,44 77.8,44.2 77.8,46 78.3,46.5 79.6,46.5 80.2,45.9 v1(80.2,45.6)
DDR_D13: U4.J13 U6.A2 | length 30.8
  L1 - TOP w0.125: U4.J13@67.2,50 v1(67.6,50.4) ; v1(80.5,42) 81,42 U6.A2@81.3,42.3
  L3 - SIG w0.125: v1(67.6,50.4) 68,50 68,47.8 68.2,47.6 68.6,47.6 68.8,47.4 68.8,47 69,46.8 69.4,46.8 70.2,46.8 70.4,46.6 70.4,46.234 70.634,46 70.641,46 77.441,39.2 78.6,39.2 78.9,39.5 78.9,40.1 79.1,40.3 79.6,40.3 79.8,40.1 79.8,39.5 80,39.3 80.5,39.3 80.7,39.5 80.7,40.2 80.9,40.4 81.4,40.4 81.6,40.2 81.6,39.6 81.9,39.3 82.7,39.3 83,39.6 83,40 82.5,40.5 82.5,41.2 82.2,41.5 81,41.5 v1(80.5,42)
DDR_D14: U4.K14 U6.B8 | length 28.8
  L1 - TOP w0.125: U4.K14@68,49.2 v1(68.4,48.8) ; v1(81.7,46.7) U6.B8@82.1,47.1
  L4 - SIG w0.125: v1(68.4,48.8) 68.8,48.4 73.7,48.4 74.1,48 74.1,45.6 74.6,45.1 79.35,45.1 79.604,45.354 79.604,45.846 79.35,46.1 75.1,46.1 74.8,46.4 74.8,47 75.1,47.3 77.55,47.3 77.75,47.1 79.4,47.1 79.8,46.7 v1(81.7,46.7)
DDR_D15: U4.K15 U6.A3 | length 30.8
  L1 - TOP w0.125: U4.K15@68.8,49.2 v1(69.2,48.8) ; v1(80.7,43.1) U6.A3@81.3,43.1
  L3 - SIG w0.125: v1(69.2,48.8) 69.7,48.8 70.1,48.4 71,48.4 71.2,48.2 71.2,47.5 71.4,47.3 71.7,47.3 72.5,48.1 72.9,48.1 73.2,47.8 73.2,47.5 72.5,46.8 72.5,46.5 72.9,46.1 73.165,46.1 73.865,46.8 74.3,46.8 74.5,46.6 74.5,46.3 73.2,45 73.2,44.75 73.55,44.4 73.8,44.4 75.1,45.7 75.4,45.7 75.8,45.3 75.8,45 74.6,43.8 74.6,43.5 74.9,43.2 75.2,43.2 76.2,44.2 76.5,44.2 76.7,44 76.7,43.659 76.149,43.108 76.149,41.951 76.4,41.7 76.7,41.7 76.9,41.9 76.9,42.8 77.1,43 78.1,43 78.3,43.2 78.3,43.6 78.5,43.8 78.9,43.8 79.1,43.6 79.1,43.2 79.3,43 80.6,43 v1(80.7,43.1)
DDR_D16: U4.B8 U8.E3 | length 28.3
  L1 - TOP w0.125: U4.B8@63.2,55.6 63.6,56 63.6,58.25 v1(67.65,62.3) ; v1(74.05,62.4) 74.25,62.6 83.05,62.6 ; 83.1,62.6 U8.E3@84.6,61.1
  L6 - BOT w0.125: v1(67.65,62.3) 67.65,61.375 68.575,60.45 70.15,60.45 72.1,62.4 v1(74.05,62.4)
DDR_D17: U4.B9 U8.F7 | length 30.7
  L1 - TOP w0.125: U4.B9@63.975,55.575 64.4,56 64.4,57.5 v1(71.2,64.3) ; v1(85,63.9) U8.F7@85.4,64.3
  L3 - SIG w0.125: v1(71.2,64.3) 77.6,64.3 77.9,64.6 77.9,66.6 78.2,66.9 78.8,66.9 79.1,66.6 79.1,64.6 79.4,64.3 84.6,64.3 v1(85,63.9)
DDR_D18: U4.C9 U8.F2 | length 28.7
  L1 - TOP w0.125: U4.C9@64,54.8 v1(64.4,55.2) ; v1(85,60.7) U8.F2@85.4,60.3
  L4 - SIG w0.125: v1(64.4,55.2) 64.8,54.8 66.966,54.8 67.2,55.034 67.2,56.175 68.625,57.6 70.566,57.6 74.266,61.3 75.962,61.3 76.5,60.762 76.5,59.625 76.725,59.4 77.05,59.4 77.275,59.625 77.275,60.975 77.9,61.6 84.05,61.6 v1@84.95,60.7
DDR_D19: U4.A9 U8.F8 | length 28.8
  L1 - TOP w0.125: U4.A9@64,56.4 64,57.9 v1(71.6,65.5) ; v1(85,64.7) U8.F8@85.4,65.1
  L4 - SIG w0.125: v1(71.6,65.5) 79.165,65.5 79.5,65.835 79.5,66.7 79.678,66.878 80.222,66.878 80.391,66.709 80.391,65.709 80.6,65.5 81.5,65.5 81.9,65.1 84.6,65.1 v1(85,64.7)
DDR_D20: U4.A10 U8.H3 | length 28.6
  L1 - TOP w0.125: U4.A10@64.8,56.4 64.8,57.066 67.784,60.05 71.85,60.05 72,60.2 72,60.7 72.158,60.858 72.742,60.858 72.9,60.7 72.9,60.216 73.066,60.05 74.15,60.05 74.3,60.2 74.3,60.6 74.482,60.782 74.918,60.782 75.1,60.6 75.1,60.25 75.3,60.05 78.25,60.05 v1(78.8,59.5) ; v1@86.6,61.5 U8.H3@87,61.1
  L4 - SIG w0.125: v1(78.8,59.5) 85.25,59.5 86.05,60.3 86.825,60.3 87,60.475 87,61.1 v1@86.7,61.4
  other v1: 86.6,61.5
DDR_D21: U4.D10 U8.H8 | length 28.8
  L1 - TOP w0.125: v1(64.4,54.4) U4.D10@64.8,54 ; v1@86.6,64.7 U8.H8@87,65.1
  L4 - SIG w0.125: v1(64.4,54.4) 64,54.8 64,55.525 72.775,64.3 86.2,64.3 v1(86.6,64.7)
DDR_D22: U4.B11 U8.G2 | length 28.8
  L1 - TOP w0.125: U4.B11@65.6,55.6 66,56 66,56.75 67.95,58.7 v1(78.35,58.7) ; U8.G2@86.2,60.3 v1@86.6,59.9
  L4 - SIG w0.125: v1(78.35,58.7) 80.375,58.7 80.63,58.445 87.395,58.445 87.95,59 88.591,59 88.875,59.284 88.875,59.614 88.588,59.9 v1(86.6,59.9) v1@86.55,59.9
DDR_D23: U4.A11 U8.H7 | length 28.8
  L1 - TOP w0.125: U4.A11@65.6,56.4 65.6,57.05 67.75,59.2 v1(77.95,59.2) ; v1@86.6,63.9 U8.H7@87,64.3
  L4 - SIG w0.125: v1(77.95,59.2) 77.95,60.5 78.45,61 79.45,61 80.15,60.3 85.35,60.3 86.2,61.15 86.2,62.3 86.6,62.7 87,62.7 87.3,63 87.3,63.6 87,63.9 v1(86.6,63.9)
DDR_D24: U4.J12 U8.D7 | length 28.3
  L1 - TOP w0.125: U4.J12@66.4,50 v1(66.8,50.4) ; v1(79.9,63.7) 80.4,63.2 83.025,63.2 83.5,63.675 83.5,64 U8.D7@83.8,64.3
  L6 - BOT w0.125: v1(66.8,50.4) 67.2,50.8 67.2,51.425 67.375,51.6 73.45,51.6 74.75,52.9 74.75,58.557 78.293,62.1 78.293,62.407 78.2,62.5 78.2,62.907 78.293,63 78.7,63 78.809,62.891 79.084,62.891 v1@79.896,63.703
DDR_D25: U4.H10 U8.C3 | length 30.8
  L1 - TOP w0.125: U4.H10@64.8,50.8 v1(65.2,51.2) ; v1(69.15,61.45) 69.15,61 69.4,60.75 70,60.75 70.3,61.05 70.3,62.3 70.5,62.5 70.975,62.5 71.2,62.275 71.2,61.65 71.4,61.45 72.25,61.45 72.5,61.7 72.5,62.2 72.7,62.4 73.075,62.4 73.3,62.175 73.3,61.65 73.5,61.45 80.543,61.45 80.693,61.6 82.5,61.6 U8.C3@83,61.1
  L3 - SIG w0.125: v1(65.2,51.2) 65.6,51.6 65.6,57.9 v1(69.15,61.45)
DDR_D26: U4.J11 U8.C8 | length 28.2
  L1 - TOP w0.125: U4.J11@65.6,50 v1(66,50.4) ; v1(82.6,65.5) U8.C8@83,65.1
  L6 - BOT w0.125: v1(66,50.4) 65.6,50.8 65.6,52.975 65.825,53.2 66.975,53.2 67.2,53.425 67.2,54.625 67.375,54.8 67.825,54.8 68,54.975 68,55.425 68.175,55.6 69.55,55.6 78.25,64.3 78.5,64.3 78.8,64 79.1,64 79.3,64.2 79.3,64.4 79,64.7 78.95,64.75 78.95,65 79.45,65.5 v1(82.6,65.5)
DDR_D27: U4.K11 U8.C2 | length 28.3
  L1 - TOP w0.125: U4.K11@65.6,49.2 v1(66,48.8) ; v1(82.6,59.9) U8.C2@83,60.3
  L6 - BOT w0.125: v1(66,48.8) 66.4,48.4 66.4,48.166 ; 66.4,48.166 66.4,47.834 66.634,47.6 72.35,47.6 73.35,48.6 74.75,48.6 75.4,49.25 76.75,49.25 79,51.5 79,54.789 79,55.95 80.75,57.7 80.75,58.4 80.35,58.8 80.35,59.3 80.55,59.5 80.55,59.9 80.95,60.3 82.15,60.3 v1@82.55,59.9
DDR_D28: U4.L13 U8.A7 | length 30.7
  L1 - TOP w0.125: U4.L13@67.2,48.4 v1(67.6,48.8) ; v1(72.3,63.05) 73.55,64.3 77.4,64.3 77.7,64.6 77.7,65.8 77.9,66 78.6,66 78.8,65.8 78.8,64.5 79,64.3 U8.A7@81.35,64.3
  L3 - SIG w0.125: v1(67.6,48.8) 67.2,49.2 67.2,52.2 67,52.4 66.6,52.4 66.4,52.6 66.4,54.6 66.1,54.9 66.1,56.85 v1(72.3,63.05)
DDR_D29: U4.L11 U8.A2 | length 28.4
  L1 - TOP w0.125: U4.L11@65.6,48.4 v1(66,48) ; U8.A2@81.4,60.3 v1(81.8,59.9)
  L6 - BOT w0.125: v1(66,48) 66,47.81 67.01,46.8 72.35,46.8 73.55,48 75.15,48 75.8,48.65 76.716,48.65 79.55,51.484 79.55,52.15 79.8,52.4 80.5,52.4 80.7,52.6 80.7,53 80.5,53.2 79.8,53.2 79.55,53.45 79.55,55.793 81.8,58.043 v1(81.8,59.9)
DDR_D30: U4.L12 U8.B8 | length 28.3
  L1 - TOP w0.125: U4.L12@66.4,48.4 v1(66.8,48.8) ; v1(81.8,64.7) U8.B8@82.2,65.1
  L6 - BOT w0.125: v1(66.8,48.8) 67.2,49.2 67.775,49.2 68,49.425 68,50.575 68.225,50.8 69.65,50.8 69.85,51 73.65,51 75.35,52.7 75.35,58.45 79.4,62.5 79.8,62.5 80.6,63.3 80.6,63.7 80.2,64.1 80.2,64.4 80.4,64.6 80.7,64.6 81.1,64.2 81.3,64.2 v1(81.8,64.7)
DDR_D31: U4.M17 U8.A3 | length 28.2
  L1 - TOP w0.125: U4.M17@70.4,47.6 71.15,47.6 71.55,48 v1(71.6,48) ; v1(80.9,61.1) U8.A3@81.4,61.1
  L6 - BOT w0.125: v1(71.6,48) 73,49.4 74.55,49.4 75.55,50.4 75.8,50.4 76.3,49.9 76.532,49.9 76.9,50.268 76.9,50.4 76.35,50.95 76.35,51.2 76.614,51.464 76.936,51.464 77.2,51.2 77.441,51.2 77.797,51.555 77.797,51.803 77.3,52.3 77.3,52.611 77.589,52.9 78.2,52.9 78.4,53.1 78.4,53.7 78.2,53.9 77.4,53.9 77.2,54.1 77.2,54.8 77.4,55 78.2,55 78.4,55.2 78.4,55.6 78.2,55.8 77.436,55.8 77.2,56.036 77.2,56.9 77.8,57.5 78.4,57.5 78.8,57.1 79.2,57.1 79.9,57.8 79.9,58.2 79.4,58.7 79.4,59.1 80,59.7 80,60.25 v1@80.85,61.1
DDR_DQM0: U4.C11 U6.E7 | length 30.7
  L1 - TOP w0.125: U4.C11@65.6,54.8 66,55.2 v1(66.8,55.2) ; v1(83.75,45.5) 84.3,45.5 84.5,45.7 U6.E7@84.5,46.3
  L3 - SIG w0.125: v1(66.8,55.2) 66.8,55.25 66.4,55.65 66.4,56.166 66.634,56.4 74.3,56.4 75.2,55.5 76.75,55.5 77.5,54.75 77.5,54.2 77.3,54 77.3,53.625 77.633,53.292 77.633,52.717 78.05,52.3 78.4,52.3 80.8,49.9 80.8,49.7 80.3,49.2 80.3,49 80.6,48.7 80.8,48.7 81.3,49.2 81.534,49.2 81.8,48.934 81.8,48.7 81.4,48.3 81.4,47.6 81.7,47.3 81.89,47.3 82.09,47.5 82.4,47.5 82.9,47 82.9,46.35 v1(83.75,45.5)
DDR_DQM1: U4.G15 U6.D3 | length 30.7
  L1 - TOP w0.125: U4.G15@68.8,51.6 v1(69.2,51.2) ; v1(83.3,42.7) U6.D3@83.7,43.1
  L3 - SIG w0.125: v1(69.2,51.2) 68.8,50.8 68.8,48.575 68.975,48.4 69.4,48.4 69.6,48.2 69.6,47.7 69.7,47.6 70.4,47.6 71.3,46.7 71.3,46.1 76.6,40.8 76.8,40.8 76.95,40.95 77.3,40.95 77.5,40.75 77.5,40 77.71,39.79 78.096,39.79 78.3,39.994 78.3,40.7 78.5,40.9 79.9,40.9 80.1,41.1 80.1,41.5 79.9,41.7 77.7,41.7 77.5,41.9 77.5,42.3 77.7,42.5 80.95,42.5 81.15,42.3 82.9,42.3 v1(83.3,42.7)
DDR_DQM2: U4.C8 U8.E7 | length 30.8
  L1 - TOP w0.125: U4.C8@63.2,54.8 62.8,55.2 62.8,58.7 67.8,63.7 v1(68.15,63.7) ; v1(84.2,63.9) U8.E7@84.6,64.3
  L3 - SIG w0.125: v1(68.15,63.7) 68.6,63.7 68.8,63.5 68.8,62.62 69.02,62.4 69.487,62.4 69.7,62.613 69.7,63.5 69.9,63.7 78.8,63.7 79.4,63.1 83.4,63.1 v1(84.2,63.9)
DDR_DQM3: U4.H11 U8.D3 | length 28.4
  L1 - TOP w0.125: U4.H11@65.6,50.8 v1(66,51.2) ; v1(77.45,62) 82.9,62 U8.D3@83.8,61.1
  L6 - BOT w0.125: v1(66,51.2) 66.4,51.6 66.4,52.2 66.6,52.4 69.65,52.4 70.025,52.025 73.025,52.025 74.05,53.05 74.05,53.8 73.4,54.45 73.4,55.55 74,56.15 74,56.85 73.3,57.55 73.3,58.05 77.25,62 v1(77.45,62)
DDR_DQS0_N: U4.B14 U6.G3 | length 30.6
  L1 - TOP w0.102: U4.B14@68,55.6 v1(68.4,56) ; v1@85.6,43.5 U6.G3@86,43.1
  L3 - SIG w0.102: v1@68.42,55.98 73.935,55.975 75.274,54.636 75.483,54.636 75.83,54.982 76.366,54.982 76.747,54.601 76.747,54.065 76.4,53.719 76.4,53.563 77.1,52.863 77.1,52.384 76.648,51.932 76.648,51.616 76.864,51.399 77.181,51.399 77.633,51.851 78.111,51.851 78.55,51.413 78.55,50.934 78.098,50.482 78.098,50.227 78.31,50.015 78.565,50.015 79.017,50.467 79.496,50.467 79.934,50.028 79.934,49.55 79.565,49.181 79.565,48.972 80.4,48.137 80.4,46.5 80.675,46.225 82.175,46.225 83.444,44.956 83.957,44.956 85,43.913 85.187,43.913 85.6,43.5 v1(85.7,43.5) v1@85.75,43.5
DDR_DQS0_P: U4.B13 U6.F3 | length 30.2
  L1 - TOP w0.102: U4.B13@67.2,55.6 v1(67.6,56) ; v1@85,43.6 U6.F3@85.4,43.2
  L3 - SIG w0.102: v1@67.775,55.975 68.131,55.619 73.831,55.619 75.139,54.311 75.618,54.311 75.964,54.657 76.231,54.657 76.421,54.467 76.421,54.2 76.075,53.853 76.075,53.428 76.775,52.728 76.775,52.519 76.323,52.067 76.323,51.481 76.73,51.074 77.316,51.074 77.768,51.526 77.977,51.526 78.225,51.278 78.225,51.069 77.773,50.617 77.773,50.092 78.175,49.69 78.7,49.69 79.152,50.142 79.361,50.142 79.609,49.894 79.609,49.685 79.24,49.316 79.24,48.837 80.075,48.003 80.075,46.365 80.54,45.9 82.04,45.9 83.31,44.63 83.78,44.63 v1@84.81,43.6
  other v1: 84.9,43.5
DDR_DQS1_N: U4.J16 U6.B7 | length 30.6
  L1 - TOP w0.102: U4.J16@69.6,50 69.913,50 70.002,49.911 70.002,49.602 v1(70,49.6) ; v1@77.09,43.54 v1(77.115,43.565) 77.25,43.7 77.25,43.858 cw(c77.881,43.858) 77.881,44.488 cw(c77.881,43.858) 78.511,43.858 78.511,43.3 cw(c77.881,43.3) 77.881,42.669 77.489,42.669 ccw(c77.489,42.344) 77.163,42.344 77.163,41.845 ccw(c77.489,41.845) 77.489,41.519 77.881,41.519 cw(c77.881,40.889) 78.511,40.889 78.511,39.5 ccw(c78.837,39.5) 78.837,39.174 ccw(c78.837,39.5) 79.163,39.5 79.163,44.213 79.7,44.75 81.45,44.75 82.198,45.498 82.198,46.202 U6.B7@82.1,46.3
  L3 - SIG w0.102: v1(70,49.6) 70.237,49.363 70.237,49.103 70.47,48.87 70.565,48.775 72.995,48.775 76.37,45.4 76.495,45.275 77.165,45.275 77.725,44.715 77.725,44.475 77.25,44 v1@77.25,43.7
DDR_DQS1_P: U4.J17 U6.C7 | length 30.5
  L1 - TOP w0.102: U4.J17@70.4,50 v1(70.8,49.6) ; v1(77.715,43.565) 77.555,43.725 77.555,43.858 cw(c77.881,43.858) 77.881,44.184 cw(c77.881,43.858) 78.206,43.858 78.206,43.3 cw(c77.881,43.3) 77.881,42.974 77.489,42.974 ccw(c77.489,42.344) 76.858,42.344 76.858,41.845 ccw(c77.489,41.845) 77.489,41.215 77.881,41.215 cw(c77.881,40.889) 78.206,40.889 ; 78.206,40.906 78.206,40.889 ; U6.C7@82.9,46.3 82.5,45.9 82.5,45.369 82.081,44.95 81.576,44.445 79.826,44.445 79.468,44.087 79.468,39.5 cw(c78.837,39.5) 78.837,38.869 cw(c78.837,39.5) 78.206,39.5 78.206,40.889
  L3 - SIG w0.102: v1(70.8,49.6) 70.563,49.363 70.563,49.237 70.7,49.1 73.13,49.1 73.205,49.025 76.63,45.6 77.3,45.6 78.05,44.85 78.05,44.34 77.575,43.865 v1@77.575,43.7
DDR_DQS2_N: U4.B10 U8.G3 | length 28.8
  L1 - TOP w0.102: U4.B10@64.8,55.6 v1(65.2,56) ; v1(85.8,61.5) U8.G3@86.2,61.1
  L4 - SIG w0.102: v1(65.2,56) 65.4,56 69.725,60.325 70.242,60.325 70.416,60.151 70.862,59.705 71.071,59.705 71.319,59.953 71.319,60.162 70.873,60.608 70.873,61.086 72.987,63.2 81.71,63.2 82.048,62.862 82.048,62.584 82.196,62.436 82.547,62.436 82.695,62.584 82.695,62.862 83.033,63.2 85.125,63.2 85.646,62.679 85.646,61.654 v1(85.8,61.5)
DDR_DQS2_P: U4.C10 U8.F3 | length 28.7
  L1 - TOP w0.102: U4.C10@64.8,54.8 v1(65.2,55.2) ; v1(85,61.5) U8.F3@85.4,61.1
  L4 - SIG w0.102: v1(65.2,55.2) 65.2,55.34 69.86,60 70.107,60 70.727,59.38 71.206,59.38 71.644,59.818 71.644,60.297 71.199,60.742 71.199,60.951 73.122,62.875 81.576,62.875 81.723,62.727 81.723,62.449 82.061,62.111 82.682,62.111 83.02,62.449 83.02,62.727 83.168,62.875 84.99,62.875 85.331,62.534 85.331,61.731 85.1,61.5 v1@84.95,61.5
DDR_DQS3_N: U4.L16 U8.B7 | length 28.4
  L1 - TOP w0.102: U4.L16@69.6,48.4 v1(70,48) ; v1(81.8,63.9) U8.B7@82.2,64.3
  L6 - BOT w0.102: v1(70,48) 70.248,48.248 70.248,48.526 70.726,49.005 71.024,49.005 72.424,50.405 74.055,50.405 76.171,52.521 76.171,53.248 ; 76.171,53.248 76.171,54.152 ; 76.171,54.748 76.171,55.652 ; 76.171,54.152 76.171,54.748 ; 76.171,55.652 76.171,58.371 79.675,61.875 80.15,61.875 80.58,62.305 84,62.305 84.2,62.505 84.2,62.805 84,63.005 82.293,63.005 81.998,63.3 81.998,63.652 81.75,63.9 v1@81.699,63.849
DDR_DQS3_P: U4.L17 U8.C7 | length 28.3
  L1 - TOP w0.102: U4.L17@70.4,48.4 v1(70.8,48) ; v1(82.6,63.9) U8.C7@83,64.3
  L6 - BOT w0.102: v1(70.8,48) 70.552,48.248 70.552,48.4 70.852,48.7 71.15,48.7 72.55,50.1 74.181,50.1 76.476,52.395 76.476,53.374 ; 76.476,53.374 76.476,54.026 ; 76.476,54.874 76.476,55.526 ; 76.476,54.026 76.476,54.874 ; 76.476,55.526 76.476,58.245 79.801,61.57 80.276,61.57 80.706,62 84.126,62 84.416,62.289 84.505,62.379 84.505,62.931 84.126,63.31 82.419,63.31 82.302,63.426 82.302,63.652 v1@82.55,63.9
DDR_RAS: U4.F13 U6.J3 U8.J3 | length 58
  L1 - TOP w0.125: U4.F13@67.2,52.4 v1(67.6,52.8) ; v1(86.9,62.2) 86.9,62.5 87.1,62.7 87.4,62.7 87.6,62.5 87.6,61.3 U8.J3@87.8,61.1 ; U6.J3@87.7,43.1 v1(88.1,43.5)
  L3 - SIG w0.125: v1(86.9,62.2) 87.4,61.7 87.4,58.45 85.6,56.65 85.6,53.55 v1(85.65,53.5) 85.65,49.55 86.5,48.7 86.5,48.2 87,47.7 87,43.75 87.55,43.2 87.85,43.2 v1@88.15,43.5
  L4 - SIG w0.125: v1(67.6,52.8) 68,53.2 68.566,53.2 68.575,53.2 68.8,53.425 68.8,53.775 69.025,54 69.55,54 70.85,55.3 72.25,55.3 73.55,56.6 75.929,56.6 76.75,55.779 76.75,53.9 76.95,53.7 77.25,53.7 77.45,53.9 77.45,54.75 77.7,55 78,55 78.25,54.75 78.25,53.95 78.5,53.7 78.8,53.7 79.05,53.95 79.05,54.75 79.3,55 79.6,55 79.85,54.75 79.85,53.75 80.1,53.5 81.6,53.5 81.85,53.75 81.85,54.107 82.443,54.7 82.857,54.7 83.15,54.407 83.15,54.193 83.843,53.5 84.9,53.5 85.35,53.95 85.35,54.6 85.75,55 86.75,55 87.111,54.639 87.111,53.911 86.7,53.5 v1(85.65,53.5)
DDR_REF: C25.1 C26.2 C28.2 C291.2 C292.2 C293.2 C294.2 R25.1 R26.2 U4.D16 U4.H16 U6.H1 U6.M8 U8.H1 U8.M8 | length 21.2
  L1 - TOP w0.125: U4.H16@69.6,50.8 v1(70,50.4) ; U4.D16@69.6,54 v1(70,53.6) ; v1(86.9,41) U6.H1@86.9,41.5 ; C294.2@86.95,57.9 87,57.95 86.9,58.05 v1(86.9,59) 86.9,59.3 U8.H1@86.963,59.363 ; v1(89.7,46.7) U6.M8@90.1,47.1 ; v1(89.8,64.7) U8.M8@90.2,65.1
  L3 - SIG w0.125: v1(70,50.4) 71.2,51.6 71.55,51.6 ; v1(70,53.6) 70,53.15 71.55,51.6 ; v1(77.35,46.7) 77.35,46.9 ; v1(78.05,47.6) 77.475,47.025 ; 71.55,51.6 71.95,51.2 73.3,51.2 77.075,47.425 77.475,47.025 ; 77.35,46.9 77.475,47.025 ; 77.35,46.9 77.475,47.025
  L6 - BOT w0.125: v1(70,53.6) 70.15,53.6 C28.2@70.75,53 ; v1(86.9,41) C292.2@87.55,41 ; v1@89.758,46.758 89.775,46.775 C291.2@89.775,47.35 ; v1(89.8,64.7) 90.35,64.7 C293.2@90.5,64.85
  other v1: 82.65,54.2 81.95,55
DDR_RESETN: R65.2 U4.E16 U6.T2 U8.T2 | length 57.2
  L1 - TOP w0.125: U4.E16@69.6,53.2 70,52.8 71.643,52.8 72.443,52 74.05,52 75.85,50.2 v1(75.85,47.9) ; U6.T2@93.3,42.3 93.9,41.7 93.9,41.2 94.35,40.75 94.95,40.75 95.2,41 95.2,41.7 95.3,41.8 v1(95.3,42.9) ; U8.T2@93.5,60.4 v1@93.9,60.8 ; R65.2@94.55,50.5 95.35,49.7 v1(95.45,49.7)
  L3 - SIG w0.125: v1(93.9,60.8) 93.9,60.75 94.95,59.7 94.95,55 95.45,54.5 v1(95.45,49.7) 95.45,48.5 95.65,48.3 95.65,45 94.85,44.2 94.85,43.7 95.3,43.25 v1(95.3,42.9)
  L4 - SIG w0.125: v1(75.85,47.9) 76.65,47.9 77.05,48.3 79.2,48.3 80,47.5 81.2,47.5 81.4,47.3 85.1,47.3 85.3,47.1 87.5,47.1 87.8,47.4 90.05,47.4 90.35,47.1 92.85,47.1 v1(95.45,49.7)
DDR_WE: U4.F15 U6.L3 U8.L3 | length 57.9
  L1 - TOP w0.125: U4.F15@68.8,52.4 v1(69.2,52.8) ; U6.L3@89.2,43.2 89.2,43.8 v1(89.7,44.3) ; U8.L3@89.4,61.1 89.4,61.3 v1@89.7,61.6
  L3 - SIG w0.125: v1@89.75,44.3 90.6,43.45 90.9,43.45 91.3,43.85 91.3,44.15 89.95,45.5 89.95,46.05 90.25,46.35 90.25,50.8 89.65,51.4 v1(89.65,52) 90.15,52 90.35,52.2 90.35,52.5 90.15,52.7 89.85,52.7 89.65,52.9 89.65,53.2 89.85,53.4 89.95,53.4 90.15,53.6 90.15,53.9 89.95,54.1 89.85,54.1 89.65,54.3 89.65,58.3 90.35,59 90.35,61.1 v1@89.75,61.7
  L4 - SIG w0.125: v1(69.2,52.8) 70.65,52.8 70.95,53.1 70.95,53.8 71.45,54.3 72.85,54.3 74.15,55.6 75.35,55.6 75.75,55.2 75.75,52.9 76.15,52.5 90.25,52.5 90.65,52.9 90.65,54.3 90.9,54.55 91.45,54.55 91.7,54.3 91.7,52.65 91.05,52 v1(89.65,52)
  other v1: 89.8,61.7
DIS_BOOT: R80.1 R251.1 U5.1 | length 21.5
  L1 - TOP w0.125: R251.1@99,11.95 101.8,14.75 v1(101.8,15) ; R80.1@102.1,30.8 102.385,30.515 102.375,30.504 U5.1@102.375,29.7 102.8,29.7 103.4,29.1 v1(103.4,27.3)
  L4 - SIG w0.125: v1(101.8,15) 101.8,16 103.4,17.6 v1(103.4,27.3)
"Earth ETH1": J13.8 J13.13 J13.14 J14.8 J14.13 J14.14 R198.2 | length 48.8
  L6 - BOT w0.5: J13.8@130.21,46.46 135.99,46.46 136.05,46.4 ; J14.8@130.21,65.33 135.98,65.33 136.05,65.4 ; 136.05,51.6 136.15,51.5 R198.2@138.5,51.5
  L6 - BOT w2.5: J13.13@136.05,34.14 136.05,46.4 136.05,51.6 J14.13@136.05,53.01 136.05,65.4 J14.14@136.05,68.76
"Earth USB": FB14.2 FB26.1 J7.0 J8.0 J9.0 J16.0 | length 30.9
  L1 - TOP w1: J16.0@2.177,5.825 2.177,7.8 ; J16.0@2.177,14.175 2.177,12.4 ; 2.352,12.225 2.177,12.4 ; 2.402,12.325 J16.0@5.225,12.325 ; J16.0@5.175,7.775 2.202,7.775 2.177,7.8 ; J9.0@77.525,2.227 J9.0@80.55,2.227 J9.0@82.85,2.227 J9.0@85.875,2.227 ; 2.177,7.8 2.177,12.4
  L6 - BOT w1: J16.0@2.177,5.825 4.425,5.825 FB26.1@4.5,5.9 ; J8.0@70.97,10.3 71.023,10.353 FB14.2@71.023,13.143 71.023,15.927 J8.0@70.97,15.98
EESCL: J4.1 R176.1 U24.43 U25.6 | length 20
  L1 - TOP w0.125: U24.43@112.95,45.1 112.95,44.35 v1(113.1,44.2)
  L4 - SIG w0.125: v1(118.7,37.27) 123.1,32.87 J4.1@123.1,31.74
  L6 - BOT w0.125: v1(113.1,44.2) 113.365,43.935 U25.6@113.365,39.8 ; U25.6@113.365,39.7 113.365,38.26 114.355,37.27 v1(118.7,37.27)
EESDA: J4.2 R179.1 U24.42 U25.5 | length 22.3
  L1 - TOP w0.125: v1(112.3,44.2) 112.45,44.35 U24.42@112.45,45.1
  L4 - SIG w0.125: v1(118.7,36) 118.7,33.9 122.13,30.47 J4.2@123.1,30.47
  L6 - BOT w0.125: U25.5@112.095,39.7 112.095,38.265 113.96,36.4 118.3,36.4 v1(118.7,36) ; U25.5@112.095,39.8 112.095,43.995 v1(112.3,44.2)
ENSPI: U27.K1 U27.K9 | length 8.9
  L1 - TOP w0.125: U27.K9@12.2,19.6 12.2,19.904 12.204,19.904 12.6,20.3 v1(12.75,20.3) ; v1(16.275,20.7) 18.5,20.7 18.9,20.3 18.9,19.9 U27.K1@18.6,19.6
  L6 - BOT w0.125: v1(12.75,20.3) 12.9,20.3 13.549,19.651 15.226,19.651 v1(16.275,20.7)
